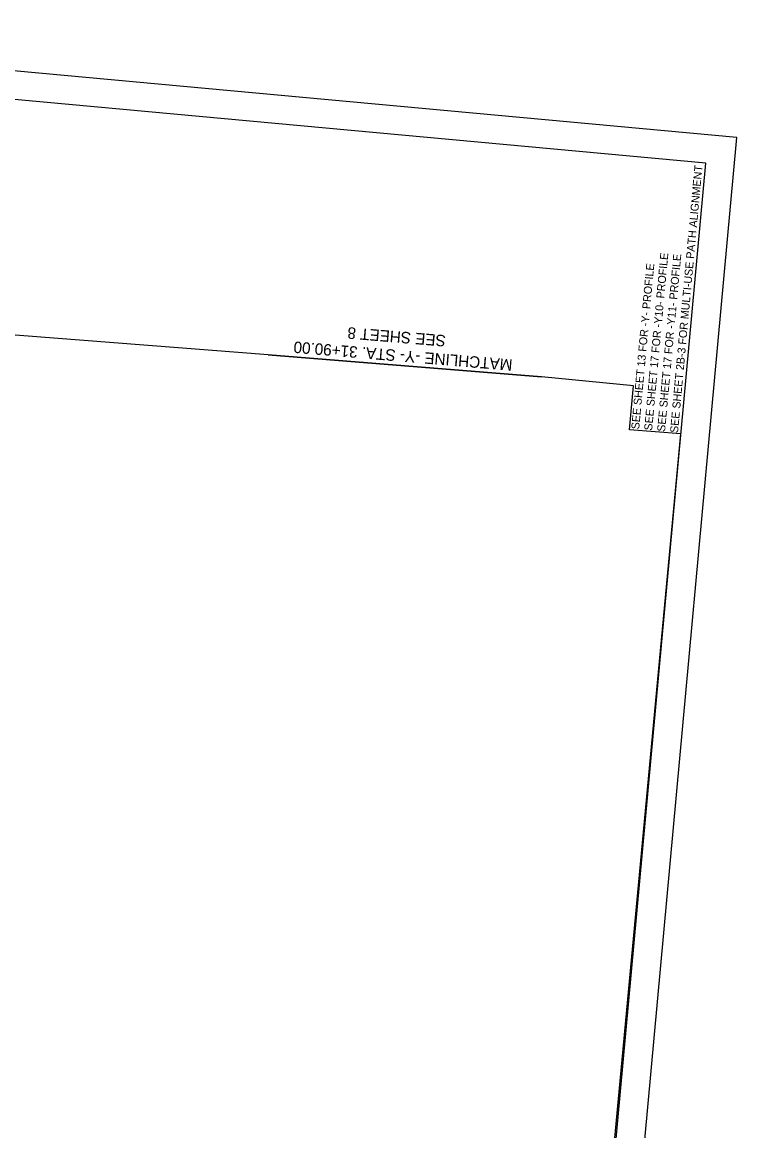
# Model space of a CAD drawing. Extents: x 2011671 to 2012922, y 444781 to 446720.
# Drawn here: x 2012296 to 2012922, y 445751 to 446720 of the extents above; entities that cross this region are included whole.
import ezdxf

# ---------------------------------------------------------------- set-up
doc = ezdxf.new("R2010")
doc.units = 0
for name, color, linetype in [('Matchline', 7, 'Continuous'), ('Matchline Text', 7, 'Continuous'), ('Prop DSN Text', 7, 'Continuous'), ('Sheet Clip Boundary CELL', 7, 'Continuous'), ('Sheet Plan And Profile CELL', 7, 'Continuous'), ('Sheet Plot Border Outside CELL', 7, 'Continuous')]:
    doc.layers.add(name, color=color, linetype=linetype)

msp = doc.modelspace()

# ---------------------------------------------------------------- linework, layer by layer
at = {"layer": 'Matchline'}
msp.add_line((2012511.43, 446429.21), (2012750.66, 446410.08), dxfattribs=at)
at = {"layer": 'Sheet Clip Boundary CELL'}
msp.add_lwpolyline([(2011937.41, 445282.88), (2012176.97, 445268.45), (2012460.6, 445251.63), (2012462.38, 445271.17), (2012773.97, 445309.09), (2012872.61, 446360.11), (2012827.76, 446363.69), (2012831.12, 446402.13), (2012750.66, 446410.08), (2012511.43, 446429.21), (2011895.9, 446477), (2011878.57, 446288.47), (2011811.27, 446294.66), (2011728.04, 445379.78), (2011768.91, 445373.07), (2011729.26, 445295.72)], close=True, dxfattribs=at)
at = {"layer": 'Sheet Plan And Profile CELL'}
msp.add_lwpolyline([(2011848.79, 446693.05), (2011711.46, 445199.36), (2012757.04, 445103.22), (2012894.38, 446596.92)], close=True, dxfattribs=at)
at = {"layer": 'Sheet Plot Border Outside CELL'}
msp.add_lwpolyline([(2012765.92, 444926.66), (2012921.57, 446619.52), (2011826.19, 446720.24), (2011670.54, 445027.38)], close=True, dxfattribs=at)

# ---------------------------------------------------------------- texts
at = {"layer": 'Matchline Text'}
for s, p in [('SEE SHEET 8', (2012667.14, 446446.44)), ('MATCHLINE -Y- STA. 31+90.00', (2012725.53, 446425.3))]:
    msp.add_text(s, height=10, rotation=175.27276, dxfattribs=at).set_placement(p)
at = {"layer": 'Prop DSN Text'}
for s, p in [('SEE SHEET 2B-3 FOR MULTI-USE PATH ALIGNMENT', (2012870.02, 446360.77)), ('SEE SHEET 17 FOR -Y10- PROFILE', (2012847.37, 446362.86)), ('SEE SHEET 17 FOR -Y11- PROFILE', (2012858.69, 446361.82)), ('SEE SHEET 13 FOR -Y- PROFILE', (2012836.04, 446363.9))]:
    msp.add_text(s, height=7, rotation=84.74666, dxfattribs=at).set_placement(p)

doc.saveas('drawing.dxf')
